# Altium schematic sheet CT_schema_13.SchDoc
size 382 x 278 mm
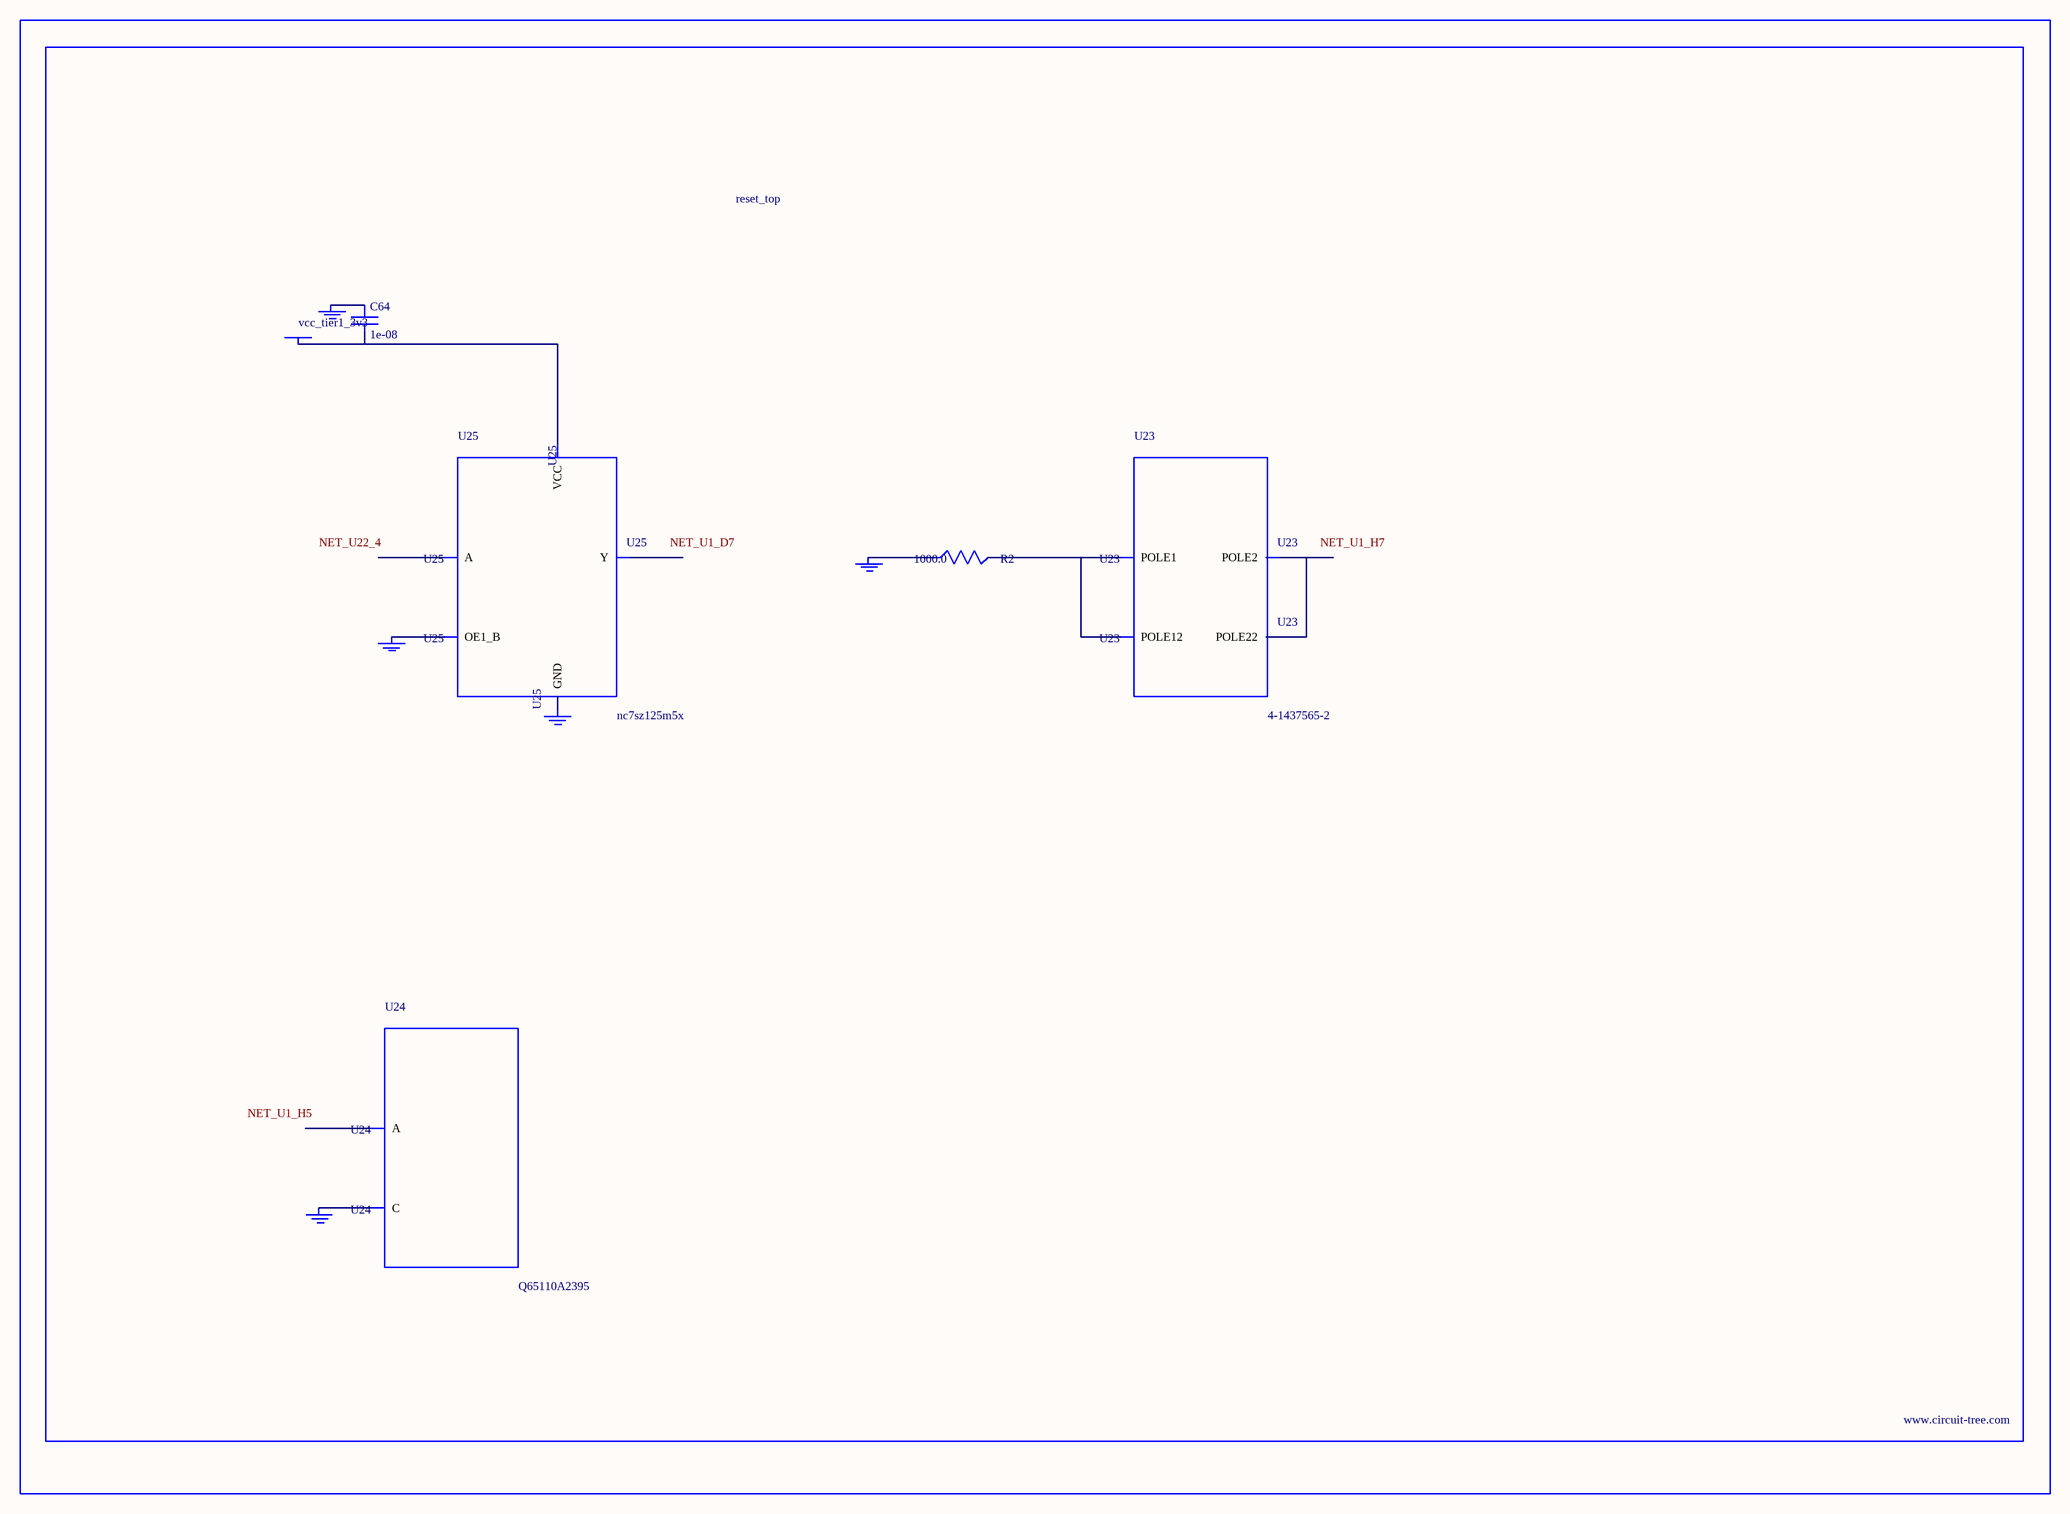
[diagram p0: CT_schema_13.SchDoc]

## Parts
BORDER12  (no value)
C64  1e-08  [C0402]
GND_INSTANCE_12_0  (no value)
GND_INSTANCE_12_1  (no value)
GND_INSTANCE_12_2  (no value)
GND_INSTANCE_12_3  (no value)
GND_INSTANCE_12_4  (no value)
POWER_INSTANCE_12_0  vcc_tier1_3v3
R2  1000.0  [R0603]
U23  4-1437565-2  [SW_4-1437565-2]
U24  Q65110A2395  [LGM67K-G1J2-24-Z]
U25  nc7sz125m5x  [NC7SZ125M5X]

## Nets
NetC64_1: C64.1 GND_INSTANCE_12_2.0(GND)
NetC64_2: C64.2 POWER_INSTANCE_12_0.0(PWR) U25.5(VCC)
NetGND_INSTANCE_12_0_0: GND_INSTANCE_12_0.0(GND) R2.1
NetGND_INSTANCE_12_1_0: GND_INSTANCE_12_1.0(GND) U24.C
NetGND_INSTANCE_12_3_0: GND_INSTANCE_12_3.0(GND) U25.1(OE1_B)
NetGND_INSTANCE_12_4_0: GND_INSTANCE_12_4.0(GND) U25.3(GND)
NetR2_2: R2.2 U23.1(POLE1) U23.2(POLE12)
NetU23_3: U23.3(POLE2) U23.4(POLE22)

Not connected (* = marked no-connect by the designer): U24 A; U25 2(A) 4(Y)

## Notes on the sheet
- Labels drawn without touching a wire or pin: NET_U1_D7, NET_U1_H5, NET_U1_H7, NET_U22_4

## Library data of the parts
BORDER12 = BORDER_PAGE12
C64 = C0402C103K3RAC
GND_INSTANCE_12_0-GND_INSTANCE_12_4 = GND
POWER_INSTANCE_12_0 = PWR
R2 = RC0603JR-071KL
